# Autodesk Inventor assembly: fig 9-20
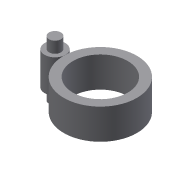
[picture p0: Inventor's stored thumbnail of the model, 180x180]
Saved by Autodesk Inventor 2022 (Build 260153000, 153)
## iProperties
Created: 2002-01
Part Number: fig 9-20
Document SubType Name: Assembly
Designer: ***
Control State: 0
Master: False
Checked Out: False
Shininess: 64.0
Length Units: 11269
Angle Units: 11279
Time Units: 11290
Mass Units: 11283
Length Display Precision: 3
Angle Display Precision: 2
Density: 0.0
Volumn: 0.0
Area: 0.0
PropertySet Name: Model Information
Author: ***
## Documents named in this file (3)
- D:\PROJECTS_2021\Resources\Part Files\c09_Inv_2022_prt\fig 9-20.iam
- D:\PROJECTS_2021\Resources\Part Files\c09_Inv_2022_prt\Part8.ipt
- D:\PROJECTS_2021\Resources\Part Files\c09_Inv_2022_prt\Part9.ipt
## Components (2 placed, 2 different names)
1. Part8:1 — Flush:1
2. Part9:1 — Flush:1
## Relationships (1: Flush 1)
- Flush:1: Part8:1 ↔ Part9:1
